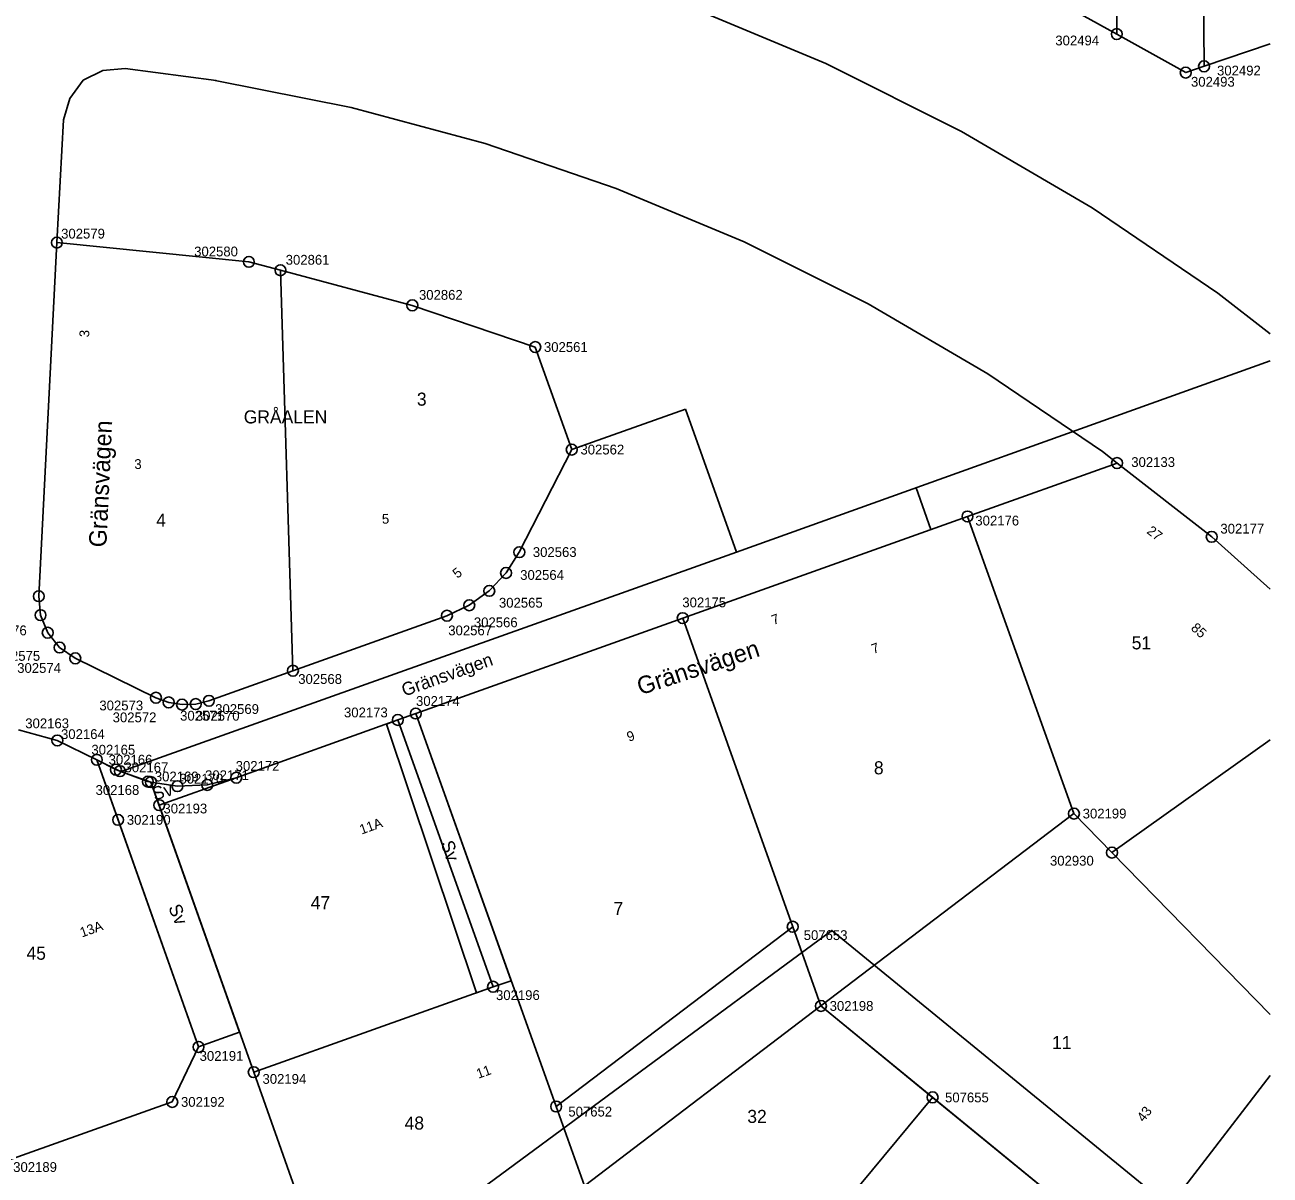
# Model space of a CAD drawing. Extents: x 141995 to 152570, y 6580184 to 6586000.
# Drawn here: x 142885.7 to 143000, y 6585263.2 to 6585368.8 of the extents above; entities that cross this region are included whole.
import ezdxf

# ---------------------------------------------------------------- set-up
doc = ezdxf.new("R2010")
doc.units = 0
for name, color, linetype in [('Level 10', 7, 'Continuous'), ('Level 13', 7, 'Continuous'), ('Level 33', 7, 'Continuous'), ('Level 34', 7, 'Continuous'), ('Level 42', 7, 'Continuous'), ('Level 43', 7, 'Continuous'), ('Level 48', 7, 'Continuous'), ('Level 5', 7, 'Continuous'), ('Level 50', 7, 'Continuous'), ('Level 51', 7, 'Continuous'), ('Level 53', 7, 'Continuous'), ('Level 54', 7, 'Continuous'), ('Level 55', 7, 'Continuous'), ('Level 6', 7, 'Continuous'), ('Level 7', 7, 'Continuous')]:
    doc.layers.add(name, color=color, linetype=linetype)

msp = doc.modelspace()

# ---------------------------------------------------------------- linework, layer by layer
at = {"layer": 'Level 10'}
for centre in [(142985.93, 6585367.95), (142993.94, 6585364.99), (142992.26, 6585364.41), (142888.66, 6585348.81), (142906.28, 6585347.04), (142909.18, 6585346.27), (142921.28, 6585343.05), (142932.56, 6585339.22), (142935.91, 6585329.81), (142985.96, 6585328.57), (142972.23, 6585323.67), (142994.64, 6585321.8), (142931.1, 6585320.39), (142929.88, 6585318.49), (142928.34, 6585316.84), (142887, 6585316.35), (142887.16, 6585314.61), (142924.46, 6585314.56), (142926.51, 6585315.52), (142946.1, 6585314.34), (142887.82, 6585313), (142888.91, 6585311.64), (142890.35, 6585310.65), (142910.32, 6585309.51), (142897.75, 6585307.03), (142898.92, 6585306.6), (142901.4, 6585306.45), (142902.61, 6585306.75), (142900.15, 6585306.4), (142921.6, 6585305.58), (142919.95, 6585304.99), (142888.7, 6585303.11), (142892.33, 6585301.33), (142894.08, 6585300.43), (142894.45, 6585300.29), (142905.12, 6585299.69), (142897.01, 6585299.33), (142897.29, 6585299.29), (142899.72, 6585298.91), (142902.46, 6585299.03), (142898.05, 6585297.17), (142982, 6585296.4), (142894.28, 6585295.82), (142985.49, 6585292.82), (142956.19, 6585286.01), (142928.69, 6585280.5), (142958.78, 6585278.74), (142901.66, 6585274.98), (142906.73, 6585272.66), (142899.25, 6585269.93), (142969.03, 6585270.35), (142934.48, 6585269.51)]:
    msp.add_circle(centre, 0.5, dxfattribs=at)
at = {"layer": 'Level 13'}
for points in [[(142946.39, 6585370.61), (142959.22, 6585365.24)], [(142959.22, 6585365.24), (142971.68, 6585359.02)], [(142891.08, 6585363.72), (142892.88, 6585364.62)], [(142892.88, 6585364.62), (142894.94, 6585364.78)], [(142894.94, 6585364.78), (142903.27, 6585363.68)], [(142889.84, 6585362.05), (142891.08, 6585363.72)], [(142903.2, 6585363.69), (142915.68, 6585361.21)], [(142889.26, 6585360.07), (142889.84, 6585362.05)], [(142915.68, 6585361.21), (142927.96, 6585357.9)], [(142888.66, 6585348.81), (142889.26, 6585360.07)], [(142971.68, 6585359.02), (142983.68, 6585351.99)], [(142927.96, 6585357.9), (142939.99, 6585353.78)], [(142939.99, 6585353.78), (142951.73, 6585348.87)], [(142983.68, 6585351.99), (142995.21, 6585344.18)], [(142951.73, 6585348.87), (142963.1, 6585343.19)], [(142995.21, 6585344.18), (143000, 6585340.43)], [(142963.1, 6585343.19), (142974.09, 6585336.77)], [(142974.09, 6585336.77), (142984.61, 6585329.63)], [(142935.91, 6585329.81), (142946.36, 6585333.52)], [(142946.36, 6585333.52), (142951.03, 6585320.4)], [(142984.61, 6585329.63), (142985.96, 6585328.57)], [(142967.51, 6585326.29), (142968.87, 6585322.47)]]:
    msp.add_lwpolyline(points, dxfattribs=at)
at = {"layer": 'Level 33'}
for points in [[(142918.91, 6585304.62), (142927.16, 6585279.95), (142928.69, 6585280.5), (142919.95, 6585304.99)], [(142919.95, 6585304.99), (142928.69, 6585280.5), (142930.36, 6585281.04), (142921.6, 6585305.58)], [(142897.29, 6585299.29), (142894.45, 6585300.29), (142892.33, 6585301.33), (142901.66, 6585274.98), (142905.43, 6585276.32)], [(142905.12, 6585299.69), (142902.46, 6585299.03), (142899.72, 6585298.91), (142897.29, 6585299.29), (142898.05, 6585297.17)]]:
    msp.add_lwpolyline(points, close=True, dxfattribs=at)
at = {"layer": 'Level 34'}
msp.add_lwpolyline([(142868.26, 6585230.02), (142870.29, 6585224.35), (142895.29, 6585230.45), (142916.07, 6585246.27), (142937.08, 6585262.24), (142958.78, 6585278.74), (142987.1, 6585255.56), (142990.76, 6585260.32), (142959.77, 6585285.68), (142924.61, 6585259.72), (142925.59, 6585257.07), (142918.16, 6585254.37), (142918, 6585254.84), (142893.13, 6585236.49)], close=True, dxfattribs=at)
at = {"layer": 'Level 5'}
for points in [[(142985.93, 6585367.95), (142977.89, 6585372.42)], [(142992.26, 6585364.41), (142985.93, 6585367.95)], [(143000, 6585367.05), (142993.94, 6585364.99)], [(142993.94, 6585364.99), (142992.26, 6585364.41)], [(142887, 6585316.35), (142888.66, 6585348.81)], [(142888.66, 6585348.81), (142906.28, 6585347.04)], [(142906.28, 6585347.04), (142909.18, 6585346.27)], [(142909.18, 6585346.27), (142921.28, 6585343.05)], [(142921.28, 6585343.05), (142932.56, 6585339.22)], [(142932.56, 6585339.22), (142935.91, 6585329.81)], [(143000, 6585337.95), (142951.03, 6585320.4)], [(142935.91, 6585329.81), (142931.1, 6585320.39)], [(142972.23, 6585323.67), (142985.96, 6585328.57)], [(142985.96, 6585328.57), (142994.64, 6585321.8)], [(142946.1, 6585314.34), (142972.23, 6585323.67)], [(142994.64, 6585321.8), (143000, 6585317.01)], [(142951.03, 6585320.4), (142894.57, 6585300.25)], [(142931.1, 6585320.39), (142929.88, 6585318.49)], [(142929.88, 6585318.49), (142928.34, 6585316.84)], [(142887.16, 6585314.61), (142887, 6585316.35)], [(142928.34, 6585316.84), (142926.51, 6585315.52)], [(142926.51, 6585315.52), (142924.46, 6585314.56)], [(142887.82, 6585313), (142887.16, 6585314.61)], [(142924.46, 6585314.56), (142910.32, 6585309.51)], [(142921.6, 6585305.58), (142946.1, 6585314.34)], [(142888.91, 6585311.64), (142887.82, 6585313)], [(142890.35, 6585310.65), (142888.91, 6585311.64)], [(142897.75, 6585307.03), (142890.35, 6585310.65)], [(142910.32, 6585309.51), (142902.61, 6585306.75)], [(142898.92, 6585306.6), (142897.75, 6585307.03)], [(142900.15, 6585306.4), (142898.92, 6585306.6)], [(142901.4, 6585306.45), (142900.15, 6585306.4)], [(142902.61, 6585306.75), (142901.4, 6585306.45)], [(142905.12, 6585299.69), (142919.95, 6585304.99)], [(142919.95, 6585304.99), (142921.6, 6585305.58)], [(142885.15, 6585304.09), (142888.7, 6585303.11)], [(142888.7, 6585303.11), (142892.33, 6585301.33)], [(142892.33, 6585301.33), (142894.08, 6585300.43)], [(142894.08, 6585300.43), (142894.45, 6585300.29)], [(142894.45, 6585300.29), (142894.57, 6585300.25)], [(142894.57, 6585300.25), (142897.01, 6585299.33)], [(142897.01, 6585299.33), (142897.29, 6585299.29)], [(142897.29, 6585299.29), (142899.72, 6585298.91)], [(142899.72, 6585298.91), (142902.46, 6585299.03)], [(142902.46, 6585299.03), (142905.12, 6585299.69)], [(143000, 6585272.35), (142987.1, 6585255.56)]]:
    msp.add_lwpolyline(points, dxfattribs=at)
at = {"layer": 'Level 6'}
for points in [[(142977.89, 6585372.42), (142985.93, 6585367.95), (142992.26, 6585364.41), (142993.94, 6585364.99), (143000, 6585367.05)], [(143000, 6585317.01), (142994.64, 6585321.8), (142985.96, 6585328.57), (142972.23, 6585323.67), (142946.1, 6585314.34), (142921.6, 6585305.58), (142919.95, 6585304.99), (142905.12, 6585299.69), (142902.46, 6585299.03), (142899.72, 6585298.91), (142897.29, 6585299.29), (142897.01, 6585299.33), (142894.45, 6585300.29), (142894.08, 6585300.43), (142892.33, 6585301.33), (142888.7, 6585303.11), (142885.15, 6585304.09)], [(142874.1, 6585158.44), (142896.91, 6585161.4), (142899.88, 6585161.78), (142919.72, 6585164.36), (142934.64, 6585166.29), (142936.38, 6585166.79), (142937.9, 6585167.8), (142939.04, 6585169.21), (142939.71, 6585170.9), (142942.33, 6585182.35), (142943.32, 6585186.07), (142944.57, 6585189.71), (142947.24, 6585196.66), (142952.47, 6585210.3), (142954.17, 6585212.53), (142956.29, 6585215.32), (142969.65, 6585232.83), (142971.77, 6585235.61), (142987.1, 6585255.56), (143000, 6585272.35)]]:
    msp.add_lwpolyline(points, dxfattribs=at)
msp.add_lwpolyline([(142932.56, 6585339.22), (142921.28, 6585343.05), (142909.18, 6585346.27), (142906.28, 6585347.04), (142888.66, 6585348.81), (142887, 6585316.35), (142887.16, 6585314.61), (142887.82, 6585313), (142888.91, 6585311.64), (142890.35, 6585310.65), (142897.75, 6585307.03), (142898.92, 6585306.6), (142900.15, 6585306.4), (142901.4, 6585306.45), (142902.61, 6585306.75), (142910.32, 6585309.51), (142924.46, 6585314.56), (142926.51, 6585315.52), (142928.34, 6585316.84), (142929.88, 6585318.49), (142931.1, 6585320.39), (142935.91, 6585329.81)], close=True, dxfattribs=at)
at = {"layer": 'Level 7'}
for points in [[(142985.93, 6585367.95), (142985.63, 6585403.11)], [(142993.94, 6585364.99), (142993.62, 6585403.11)], [(142910.32, 6585309.51), (142909.18, 6585346.27)], [(142982, 6585296.4), (142972.23, 6585323.67)], [(142946.1, 6585314.34), (142956.19, 6585286.01)], [(142919.95, 6585304.99), (142928.69, 6585280.5)], [(142921.6, 6585305.58), (142934.48, 6585269.51)], [(142985.49, 6585292.82), (143000, 6585303.17)], [(142894.28, 6585295.82), (142892.33, 6585301.33)], [(142897.29, 6585299.29), (142898.05, 6585297.17)], [(142898.05, 6585297.17), (142906.73, 6585272.66)], [(142901.66, 6585274.98), (142894.28, 6585295.82)], [(142958.78, 6585278.74), (142982, 6585296.4)], [(142985.49, 6585292.82), (142982, 6585296.4)], [(143000, 6585277.94), (142985.49, 6585292.82)], [(142934.48, 6585269.51), (142956.19, 6585286.01)], [(142956.19, 6585286.01), (142958.78, 6585278.74)], [(142928.69, 6585280.5), (142906.73, 6585272.66)], [(142969.03, 6585270.35), (142958.78, 6585278.74)], [(142899.25, 6585269.93), (142901.66, 6585274.98)], [(142906.73, 6585272.66), (142916.07, 6585246.27)], [(142952.49, 6585250.41), (142969.03, 6585270.35)], [(142987.1, 6585255.56), (142969.03, 6585270.35)], [(142883.23, 6585264.26), (142899.25, 6585269.93)], [(142934.48, 6585269.51), (142937.08, 6585262.24)]]:
    msp.add_lwpolyline(points, dxfattribs=at)

# ---------------------------------------------------------------- texts
at = {"layer": 'Level 42'}
msp.add_text('Gränsvägen', height=1.2, rotation=19.5697, dxfattribs=at).set_placement((142920.55, 6585307.13))
at = {"layer": 'Level 43'}
for rotation, p in [(87.285, (142893.19, 6585320.81)), (18.1256, (142942.21, 6585307.25))]:
    msp.add_text('Gränsvägen', height=1.6, rotation=rotation, dxfattribs=at).set_placement(p)
at = {"layer": 'Level 48'}
for rotation, p in [(16.7726, (142897.63, 6585297.59)), (288.4886, (142923.88, 6585293.69)), (293.1114, (142898.86, 6585287.78))]:
    msp.add_text('Sv', height=1.2, rotation=rotation, dxfattribs=at).set_placement(p)
at = {"layer": 'Level 50'}
msp.add_text('GRÅALEN', height=1.2, rotation=0.0493, dxfattribs=at).set_placement((142905.81, 6585332.21))
at = {"layer": 'Level 51'}
for s, p in [('3', (142921.7, 6585333.84)), ('4', (142897.78, 6585322.74)), ('51', (142987.3, 6585311.47)), ('8', (142963.64, 6585300)), ('47', (142911.96, 6585287.62)), ('7', (142939.75, 6585287.09)), ('45', (142885.87, 6585282.98)), ('11', (142979.99, 6585274.78)), ('48', (142920.57, 6585267.39))]:
    msp.add_text(s, height=1.2, rotation=0.0493, dxfattribs=at).set_placement(p)
msp.add_text('32', height=1.2, dxfattribs=at).set_placement((142952.02, 6585268))
at = {"layer": 'Level 53'}
for s, p in [('302494', (142980.29, 6585366.91)), ('302492', (142995.13, 6585364.15)), ('302493', (142992.74, 6585363.12)), ('302579', (142889.05, 6585349.18)), ('302580', (142901.26, 6585347.54)), ('302861', (142909.66, 6585346.78)), ('302862', (142921.89, 6585343.56)), ('302561', (142933.36, 6585338.77)), ('302562', (142936.71, 6585329.36)), ('302133', (142987.26, 6585328.21)), ('302176', (142972.95, 6585322.84)), ('302177', (142995.44, 6585322.1)), ('302563', (142932.34, 6585319.95)), ('302564', (142931.18, 6585317.85)), ('302565', (142929.23, 6585315.3)), ('302175', (142946.06, 6585315.33)), ('302566', (142926.93, 6585313.5)), ('302576', (142881.88, 6585312.76)), ('302567', (142924.58, 6585312.76)), ('302575', (142883.11, 6585310.42)), ('302574', (142885.02, 6585309.31)), ('302568', (142910.81, 6585308.3)), ('302174', (142921.62, 6585306.28)), ('302573', (142892.56, 6585305.87)), ('302571', (142899.97, 6585304.93)), ('302570', (142901.41, 6585304.92)), ('302569', (142903.19, 6585305.54)), ('302173', (142915.01, 6585305.23)), ('302163', (142885.76, 6585304.23)), ('302572', (142893.78, 6585304.78)), ('302164', (142889.04, 6585303.24)), ('302165', (142891.83, 6585301.81)), ('302166', (142893.41, 6585300.89)), ('302172', (142905.07, 6585300.32)), ('302167', (142894.87, 6585300.19)), ('302169', (142897.65, 6585299.35)), ('302170', (142899.91, 6585299.15)), ('302171', (142902.26, 6585299.47)), ('302168', (142892.21, 6585298.11)), ('302193', (142898.44, 6585296.41)), ('302199', (142982.8, 6585295.95)), ('302190', (142895.08, 6585295.37)), ('302930', (142979.8, 6585291.62)), ('302196', (142928.96, 6585279.28)), ('302198', (142959.58, 6585278.29)), ('302191', (142901.76, 6585273.7)), ('302194', (142907.53, 6585271.59)), ('302192', (142900.05, 6585269.48)), ('302189', (142884.65, 6585263.5))]:
    msp.add_text(s, height=0.9, rotation=0.0493, dxfattribs=at).set_placement(p)
for s, p in [('507653', (142957.2, 6585284.79)), ('507655', (142970.17, 6585269.89)), ('507652', (142935.6, 6585268.59))]:
    msp.add_text(s, height=0.9, dxfattribs=at).set_placement(p)
at = {"layer": 'Level 54'}
for s, rotation, p in [('3', 1.4953, (142895.78, 6585328.02)), ('5', 1.3353, (142918.5, 6585323)), ('85', 318.2079, (142992.67, 6585313.33)), ('7', 19.5407, (142963.6, 6585311.04)), ('9', 19.4267, (142941.15, 6585302.98)), ('11A', 19.5497, (142916.62, 6585294.47)), ('13A', 19.4437, (142890.96, 6585285.02)), ('11', 19.6507, (142927.34, 6585272.05)), ('43', 52.4606, (142988.4, 6585268.02))]:
    msp.add_text(s, height=0.9, rotation=rotation, dxfattribs=at).set_placement(p)
at = {"layer": 'Level 55'}
for s, rotation, p in [('3', 87.073, (142891.62, 6585340.1)), ('27', 322.0257, (142988.61, 6585322.19)), ('5', 38.7327, (142925.42, 6585317.94)), ('7', 19.6537, (142954.43, 6585313.7))]:
    msp.add_text(s, height=0.9, rotation=rotation, dxfattribs=at).set_placement(p)

doc.saveas('drawing.dxf')
